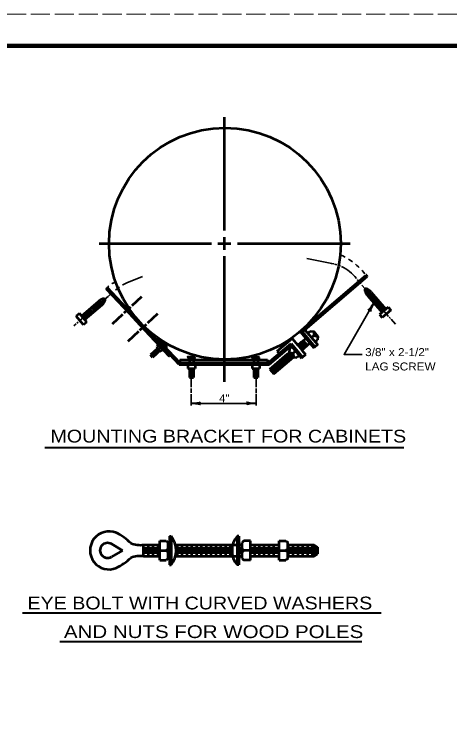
# Model space of a CAD drawing. Extents: x -1 to 679, y 0 to 440.
# Drawn here: x 353.6 to 490.2, y 220.2 to 440.2 of the extents above; entities that cross this region are included whole.
import ezdxf

# ---------------------------------------------------------------- set-up
doc = ezdxf.new("R2010")
doc.units = 0
doc.header["$PDMODE"] = 32
doc.header["$PDSIZE"] = 0.5
doc.linetypes.add('LONG_DASHED', pattern=[7.5, 6, -1.5])
doc.linetypes.add('SHORT_DASHED', pattern=[2.7, 1.5, -1.2])
doc.layers.add('1', color=7, linetype='Continuous', lineweight=53)
doc.layers.add('61', color=7, linetype='Continuous', lineweight=35)

msp = doc.modelspace()

# ---------------------------------------------------------------- linework, layer by layer
at = {"layer": '1'}
for p, q in [((419.561, 372.368), (419.561, 407.928)), ((419.561, 368.308), (419.561, 370.348)), ((380.261, 368.308), (415.501, 368.308)), ((417.481, 368.308), (421.501, 368.308)), ((419.561, 366.328), (419.561, 368.308)), ((423.581, 368.308), (458.881, 368.308)), ((443.221, 340.688), (463.921, 358.368)), ((443.941, 340.628), (464.261, 357.988)), ((462.401, 357.048), (462.721, 356.668)), ((405.341, 330.368), (382.921, 354.408)), ((460.861, 355.748), (461.181, 355.368)), ((388.101, 348.108), (382.561, 354.048)), ((463.541, 353.388), (464.301, 354.048)), ((463.661, 353.068), (464.421, 353.968)), ((464.081, 352.348), (465.081, 353.488)), ((464.321, 352.068), (468.901, 346.708)), ((464.621, 351.728), (465.621, 352.888)), ((465.161, 351.108), (466.161, 352.268)), ((465.481, 353.048), (470.061, 347.688)), ((380.101, 350.148), (374.741, 345.568)), ((379.741, 349.848), (380.901, 348.848)), ((380.361, 350.388), (381.501, 349.388)), ((381.081, 350.828), (381.981, 350.048)), ((381.401, 350.948), (382.061, 350.188)), ((390.601, 348.888), (393.661, 351.748)), ((465.681, 350.488), (466.681, 351.648)), ((466.201, 349.868), (467.221, 351.028)), ((466.741, 349.248), (467.741, 350.408)), ((381.061, 348.988), (375.721, 344.428)), ((377.261, 347.728), (378.421, 346.728)), ((377.881, 348.268), (379.041, 347.268)), ((378.501, 348.788), (379.661, 347.788)), ((379.121, 349.328), (380.281, 348.328)), ((388.101, 346.548), (390.181, 348.468)), ((388.461, 348.448), (388.101, 348.108)), ((389.641, 346.448), (388.101, 348.108)), ((467.261, 348.628), (468.281, 349.788)), ((467.801, 348.008), (468.801, 349.168)), ((470.821, 348.348), (468.141, 346.068)), ((468.321, 347.388), (469.341, 348.548)), ((469.561, 348.268), (468.421, 347.288)), ((470.821, 348.348), (471.641, 347.388)), ((374.081, 346.328), (373.121, 345.528)), ((375.401, 342.828), (373.121, 345.528)), ((376.361, 343.648), (374.081, 346.328)), ((376.281, 344.908), (375.301, 346.068)), ((375.401, 346.148), (376.561, 345.148)), ((376.021, 346.668), (377.181, 345.668)), ((376.641, 347.208), (377.801, 346.208)), ((384.461, 343.148), (387.741, 346.208)), ((390.001, 346.788), (389.641, 346.448)), ((393.081, 342.748), (389.641, 346.448)), ((395.561, 343.468), (398.621, 346.328)), ((468.141, 346.068), (468.961, 345.108)), ((471.641, 347.388), (468.961, 345.108)), ((376.361, 343.648), (375.401, 342.828)), ((393.061, 341.148), (395.121, 343.068)), ((393.441, 343.108), (393.081, 342.748)), ((395.001, 341.448), (394.641, 341.088)), ((389.401, 337.748), (392.681, 340.808)), ((443.221, 340.688), (447.481, 335.628)), ((443.941, 340.628), (447.861, 335.948)), ((445.641, 340.148), (446.401, 340.808)), ((446.801, 338.788), (447.561, 339.468)), ((447.481, 340.728), (448.781, 339.188)), ((399.181, 337.708), (398.621, 338.308)), ((405.521, 330.908), (398.641, 338.268)), ((433.241, 330.868), (440.421, 337.008)), ((436.041, 334.588), (440.721, 338.588)), ((440.421, 337.008), (444.001, 332.708)), ((443.081, 336.968), (444.361, 335.408)), ((443.641, 337.448), (444.941, 335.908)), ((443.681, 336.828), (444.341, 336.048)), ((443.801, 334.928), (446.281, 337.048)), ((444.221, 337.948), (444.981, 338.588)), ((444.221, 337.948), (445.521, 336.388)), ((444.261, 337.308), (444.921, 336.548)), ((447.941, 337.468), (448.701, 338.108)), ((398.481, 334.028), (397.801, 334.748)), ((398.661, 334.528), (398.341, 334.888)), ((398.921, 336.508), (398.361, 336.008)), ((398.521, 335.448), (399.221, 334.708)), ((399.601, 335.768), (399.041, 335.268)), ((400.281, 335.028), (399.721, 334.528)), ((436.041, 334.588), (436.681, 333.808)), ((440.681, 335.908), (439.901, 335.248)), ((441.801, 334.548), (441.041, 333.908)), ((443.121, 336.328), (443.761, 335.568)), ((397.021, 332.628), (396.321, 333.368)), ((397.261, 333.208), (396.901, 333.588)), ((397.801, 333.368), (397.101, 334.108)), ((397.981, 333.868), (397.621, 334.228)), ((409.161, 332.748), (409.161, 332.248)), ((409.801, 331.868), (410.301, 332.748)), ((429.341, 332.728), (429.341, 332.228)), ((429.961, 331.868), (430.481, 332.728)), ((435.001, 327.428), (441.141, 332.648)), ((438.101, 332.708), (439.421, 331.188)), ((438.681, 333.208), (439.981, 331.668)), ((438.721, 332.568), (439.381, 331.808)), ((439.261, 333.688), (440.561, 332.168)), ((439.301, 333.068), (439.941, 332.308)), ((439.821, 334.188), (441.141, 332.648)), ((439.861, 333.568), (440.521, 332.788)), ((442.941, 333.208), (442.181, 332.568)), ((444.961, 333.528), (443.621, 332.388)), ((405.341, 330.368), (433.481, 330.368)), ((405.521, 331.868), (432.981, 331.868)), ((405.521, 331.868), (405.521, 330.868)), ((405.521, 330.868), (433.241, 330.868)), ((408.041, 330.368), (408.041, 329.108)), ((408.541, 331.628), (408.541, 331.128)), ((409.801, 331.628), (409.801, 331.128)), ((410.301, 330.368), (410.301, 329.108)), ((428.201, 330.348), (428.201, 329.088)), ((428.701, 331.608), (428.701, 331.108)), ((429.961, 331.608), (429.961, 331.108)), ((430.481, 330.348), (430.481, 329.088)), ((432.981, 331.868), (432.981, 330.868)), ((435.221, 330.268), (436.541, 328.728)), ((435.801, 330.748), (437.121, 329.228)), ((435.841, 330.128), (436.501, 329.348)), ((436.381, 331.248), (437.681, 329.708)), ((436.421, 330.608), (437.081, 329.848)), ((436.961, 331.728), (438.261, 330.208)), ((437.001, 331.108), (437.641, 330.348)), ((437.521, 332.228), (438.841, 330.688)), ((437.561, 331.588), (438.221, 330.828)), ((438.141, 332.088), (438.801, 331.328)), ((408.041, 329.108), (410.301, 329.108)), ((408.541, 329.108), (408.541, 326.328)), ((408.541, 328.348), (409.801, 328.348)), ((408.781, 328.748), (409.541, 328.748)), ((408.781, 328.008), (409.541, 328.008)), ((409.801, 329.108), (409.801, 326.328)), ((428.201, 329.088), (430.481, 329.088)), ((428.701, 329.088), (428.701, 326.328)), ((428.701, 328.348), (429.961, 328.348)), ((428.961, 328.748), (429.721, 328.748)), ((428.961, 327.988), (429.721, 327.988)), ((429.961, 329.088), (429.961, 326.328)), ((433.701, 328.948), (435.001, 327.428)), ((434.081, 329.288), (435.381, 327.748)), ((434.081, 329.288), (435.381, 327.748)), ((434.661, 329.768), (435.961, 328.228)), ((434.701, 329.148), (435.341, 328.368)), ((435.261, 329.628), (435.921, 328.868)), ((408.541, 327.588), (409.801, 327.588)), ((408.541, 326.828), (409.801, 326.828)), ((408.541, 326.328), (409.801, 326.328)), ((408.781, 327.188), (409.541, 327.188)), ((428.701, 327.568), (429.961, 327.568)), ((428.701, 326.828), (429.961, 326.828)), ((428.701, 326.328), (429.961, 326.328)), ((428.961, 327.188), (429.721, 327.188)), ((399.251, 275.106), (401.271, 275.106)), ((402.271, 276.606), (402.271, 267.546)), ((402.271, 276.606), (402.791, 276.606)), ((402.791, 276.606), (402.791, 267.546)), ((423.511, 276.606), (423.511, 267.546)), ((424.011, 276.606), (423.511, 276.606)), ((424.011, 276.606), (424.011, 267.546)), ((425.631, 275.126), (425.031, 274.606)), ((427.651, 275.126), (425.631, 275.126)), ((436.711, 275.126), (438.731, 275.126)), ((438.731, 275.126), (439.331, 274.606)), ((387.591, 272.106), (384.091, 274.126)), ((394.211, 270.306), (394.211, 273.846)), ((394.211, 273.846), (399.231, 273.846)), ((394.971, 271.066), (394.971, 273.086)), ((395.731, 270.306), (395.731, 273.846)), ((396.491, 271.066), (396.491, 273.086)), ((397.231, 270.306), (397.231, 273.846)), ((397.991, 271.066), (397.991, 273.086)), ((398.751, 270.306), (398.751, 273.846)), ((401.871, 272.586), (401.871, 274.606)), ((401.871, 273.846), (402.251, 273.846)), ((404.171, 273.846), (424.971, 273.846)), ((404.791, 270.306), (404.791, 273.846)), ((405.551, 271.066), (405.551, 273.086)), ((406.311, 270.306), (406.311, 273.846)), ((407.071, 271.066), (407.071, 273.086)), ((407.831, 270.306), (407.831, 273.846)), ((408.571, 271.066), (408.571, 273.086)), ((409.331, 270.306), (409.331, 273.846)), ((410.091, 271.066), (410.091, 273.086)), ((410.851, 270.306), (410.851, 273.846)), ((411.611, 271.066), (411.611, 273.086)), ((412.351, 270.306), (412.351, 273.846)), ((413.111, 271.066), (413.111, 273.086)), ((413.871, 270.306), (413.871, 273.846)), ((414.631, 271.066), (414.631, 273.086)), ((415.391, 270.306), (415.391, 273.846)), ((416.131, 271.066), (416.131, 273.086)), ((416.891, 270.306), (416.891, 273.846)), ((417.651, 271.066), (417.651, 273.086)), ((418.411, 270.306), (418.411, 273.846)), ((419.171, 271.066), (419.171, 273.086)), ((419.911, 270.306), (419.911, 273.846)), ((420.671, 271.066), (420.671, 273.086)), ((421.431, 270.306), (421.431, 273.846)), ((424.471, 271.066), (424.471, 273.086)), ((425.031, 272.606), (425.031, 274.606)), ((427.571, 273.846), (436.671, 273.846)), ((428.231, 271.066), (428.231, 273.086)), ((428.991, 270.306), (428.991, 273.846)), ((429.751, 271.066), (429.751, 273.086)), ((430.511, 270.306), (430.511, 273.846)), ((431.251, 271.066), (431.251, 273.086)), ((432.011, 270.306), (432.011, 273.846)), ((432.771, 271.066), (432.771, 273.086)), ((433.531, 270.306), (433.531, 273.846)), ((434.291, 271.066), (434.291, 273.086)), ((435.031, 270.306), (435.031, 273.846)), ((435.791, 271.066), (435.791, 273.086)), ((439.291, 273.846), (447.631, 273.846)), ((439.331, 272.606), (439.331, 274.606)), ((439.571, 270.306), (439.571, 273.846)), ((440.331, 271.066), (440.331, 273.086)), ((441.091, 270.306), (441.091, 273.846)), ((441.851, 271.066), (441.851, 273.086)), ((442.591, 270.306), (442.591, 273.846)), ((443.351, 271.066), (443.351, 273.086)), ((444.111, 270.306), (444.111, 273.846)), ((444.871, 271.066), (444.871, 273.086)), ((445.631, 270.306), (445.631, 273.846)), ((446.371, 271.066), (446.371, 273.086)), ((447.131, 270.306), (447.131, 273.846)), ((447.631, 273.846), (447.631, 270.306)), ((447.631, 273.846), (448.651, 273.086)), ((448.151, 273.466), (448.151, 270.686)), ((448.651, 273.086), (448.651, 271.066)), ((387.591, 272.106), (384.091, 270.086)), ((399.251, 272.086), (401.271, 272.086)), ((401.871, 272.586), (401.871, 271.566)), ((401.871, 269.566), (401.871, 271.566)), ((425.031, 272.606), (425.031, 271.586)), ((425.031, 269.566), (425.031, 271.586)), ((427.651, 272.086), (425.631, 272.086)), ((436.711, 272.086), (438.731, 272.086)), ((439.331, 272.606), (439.331, 271.586)), ((439.331, 269.566), (439.331, 271.586)), ((447.631, 270.306), (448.651, 271.066)), ((394.211, 270.306), (399.231, 270.306)), ((399.251, 269.046), (401.271, 269.046)), ((401.871, 269.566), (401.271, 269.046)), ((401.871, 270.306), (402.271, 270.306)), ((404.171, 270.306), (425.031, 270.306)), ((425.031, 269.566), (425.631, 269.066)), ((427.651, 269.066), (425.631, 269.066)), ((436.711, 269.066), (438.731, 269.066)), ((439.331, 269.566), (438.731, 269.066)), ((439.331, 270.306), (447.631, 270.306)), ((402.271, 267.546), (402.791, 267.546)), ((424.011, 267.546), (423.511, 267.546))]:
    msp.add_line(p, q, dxfattribs=at)
at = {"layer": '1', "lineweight": 13}
for p, q in [((421.501, 368.308), (421.521, 368.308)), ((393.861, 341.928), (394.221, 342.248))]:
    msp.add_line(p, q, dxfattribs=at)
at = {"layer": '1', "lineweight": 35}
for p, q in [((445.341, 363.568), (453.201, 362.048)), ((452.961, 362.088), (453.761, 361.928)), ((393.841, 357.928), (388.921, 355.988)), ((461.301, 356.788), (462.281, 355.628)), ((462.601, 355.248), (464.701, 352.808)), ((464.421, 353.228), (464.821, 352.768)), ((465.281, 352.108), (470.961, 345.468)), ((378.861, 348.108), (383.161, 351.768)), ((378.141, 347.488), (378.601, 347.888)), ((373.881, 343.848), (377.981, 347.348)), ((373.281, 343.348), (373.681, 343.668)), ((471.161, 345.248), (471.561, 344.768)), ((471.721, 344.588), (473.081, 342.988)), ((372.301, 342.508), (373.081, 343.168)), ((409.121, 326.328), (409.121, 323.248)), ((429.421, 326.368), (429.421, 323.288)), ((409.121, 322.828), (409.121, 321.508)), ((429.421, 322.868), (429.421, 321.548)), ((409.121, 321.128), (409.121, 317.508)), ((429.421, 321.168), (429.421, 317.548)), ((409.121, 318.208), (429.361, 318.208))]:
    msp.add_line(p, q, dxfattribs=at)
at = {"layer": '1', "lineweight": 40}
for p, q in [((363.269, 304.328), (475.717, 304.328)), ((356.23, 252.546), (468.616, 252.546)), ((367.972, 243.526), (462.577, 243.526))]:
    msp.add_line(p, q, dxfattribs=at)
at = {"layer": '1'}
for points in [[(419.561, 324.908), (419.561, 332.108), (419.561, 364.308)], [(402.161, 333.028), (394.641, 341.088), (393.081, 342.748)], [(444.701, 341.288), (448.641, 336.608), (447.481, 335.628)], [(446.401, 340.808), (447.481, 340.728), (447.561, 339.468), (448.781, 339.188), (448.701, 338.108)], [(440.721, 338.588), (442.501, 336.468), (443.801, 334.928), (444.961, 333.528)], [(442.501, 336.468), (443.641, 337.448), (444.221, 337.948)], [(398.521, 335.448), (397.421, 334.408), (396.321, 333.368)], [(399.221, 334.708), (398.121, 333.668), (397.021, 332.628)], [(398.361, 336.008), (398.521, 335.448), (399.041, 335.268), (399.221, 334.708), (399.721, 334.528)], [(433.481, 330.368), (440.381, 336.248), (443.621, 332.388)], [(439.901, 335.248), (439.821, 334.188), (441.041, 333.908), (441.141, 332.648), (442.181, 332.568)], [(408.541, 331.868), (408.041, 332.748), (410.301, 332.748)], [(428.701, 331.868), (428.201, 332.728), (430.481, 332.728)], [(433.701, 328.948), (439.261, 333.688), (439.821, 334.188)], [(399.251, 269.046), (399.251, 272.086), (399.251, 275.106)], [(401.271, 275.106), (401.871, 274.606), (401.871, 272.586), (401.271, 272.086), (401.871, 271.566)], [(427.651, 269.066), (427.651, 272.086), (427.651, 275.126)], [(436.711, 269.066), (436.711, 272.086), (436.711, 275.126)], [(425.031, 272.606), (425.631, 272.086), (425.031, 271.586)], [(439.331, 272.606), (438.731, 272.086), (439.331, 271.586)], [(427.611, 270.306), (436.671, 270.306), (436.711, 270.306)]]:
    msp.add_lwpolyline(points, dxfattribs=at)
at = {"layer": '1', "lineweight": 35}
msp.add_lwpolyline([(462.701, 333.548), (457.021, 333.548), (466.341, 349.708)], dxfattribs=at)
at = {"layer": '1'}
msp.add_circle((419.664, 368.287), 36.288, dxfattribs=at)
at = {"layer": '1', "linetype": 'SHORT_DASHED', "lineweight": 35}
for centre, radius, start, end in [((446.674, 345.165), 21.69, 39.09076, 64.25674), ((387.401, 350.48), 6.088, 107.18277, 136.93055), ((399.617, 335.348), 23.253, 117.40174, 135.04708)]:
    msp.add_arc(centre, radius, start, end, dxfattribs=at)
at = {"layer": '1', "lineweight": 35}
for start, end in [(72.09704, 75.39826), (66.7088, 70.55356), (37.97532, 65.20978), (34.61481, 35.37094)]:
    msp.add_arc((450.83, 349.56), 12.719, start, end, dxfattribs=at)
at = {"layer": '1'}
for centre, radius, start, end in [((463.949, 358.221), 0.147, 341.35274, 99.6479), ((464.227, 358.127), 0.147, 161.35274, 279.6479), ((464.113, 358.03), 0.147, 341.35274, 99.6479), ((382.882, 354.256), 0.147, 75.35274, 193.6479), ((382.777, 354.364), 0.147, 255.35274, 13.6479), ((382.702, 354.08), 0.147, 75.35274, 193.6479), ((464.491, 353.662), 0.994, 154.26025, 195.83671), ((466.584, 354.331), 3.191, 197.13743, 224.94055), ((463.878, 353.139), 0.994, 64.26025, 105.83671), ((462.617, 350.829), 3.625, 37.7559, 62.16939), ((382.348, 347.893), 3.191, 107.13743, 134.94055), ((378.847, 351.859), 3.625, 307.7559, 332.16939), ((381.68, 349.985), 0.994, 64.26025, 105.83671), ((381.157, 350.598), 0.994, 334.26025, 15.83671), ((398.387, 337.996), 0.147, 73.35274, 191.6479), ((398.573, 338.166), 0.147, 73.35274, 191.6479), ((398.471, 338.277), 0.147, 253.35274, 11.6479), ((398.471, 338.277), 0.147, 11.56977, 11.63706), ((399.609, 335.794), 1.805, 346.12036, 99.8792), ((402.286, 333.096), 0.147, 86.35274, 204.6479), ((402.162, 333.181), 0.147, 266.35274, 24.6479), ((402.304, 333.389), 0.147, 266.35274, 24.6479), ((383.37, 272.117), 5.96, 67.37581, 292.62419), ((379.006, 263.665), 15.46, 43.69833, 64.49446), ((397.211, 272.078), 7.185, 320.85375, 39.14625), ((429.074, 272.078), 7.185, 140.85375, 219.14625), ((382.885, 272.11), 2.352, 58.9871, 301.0129), ((393.397, 283.677), 9.87, 250.99574, 274.75423), ((377.334, 283.147), 18.511, 296.74116, 313.96028), ((393.397, 260.49), 9.87, 85.24577, 109.00426)]:
    msp.add_arc(centre, radius, start, end, dxfattribs=at)
at = {"layer": '1', "lineweight": 40}
for centre, major_axis, ratio, start_param, end_param in [((465.596, 348.84), (-1.039, -1.445), 0.07063, 6.2823074, 8.5597026), ((466.037, 348.62), (0.764, 1.638), 0.122415, 0.8963533, 3.1415927), ((410.214, 318.482), (-1.8, -0.157), 0.122415, 0.8963533, 3.1415927), ((410.244, 317.99), (1.77, -0.177), 0.07063, 6.2823074, 8.5597026), ((428.262, 317.925), (1.8, 0.157), 0.122415, 0.8963533, 3.1415927), ((428.233, 318.417), (-1.77, 0.177), 0.07063, 6.2823074, 8.5597026)]:
    msp.add_ellipse(centre, major_axis=major_axis, ratio=ratio, start_param=start_param, end_param=end_param, dxfattribs=at)
at = {"layer": '1'}
msp.add_point((398.621, 338.308), dxfattribs=at)
at = {"layer": '61', "linetype": 'LONG_DASHED', "lineweight": 13}
msp.add_line((-1.129, 440.242), (678.891, 440.242), dxfattribs=at)
at = {"layer": '61', "lineweight": 158}
msp.add_lwpolyline([(667.911, 430.242), (28.871, 430.242), (28.871, 10.222)], dxfattribs=at)

# ---------------------------------------------------------------- texts
at = {"layer": '1'}
for s, height, width, p in [('3/8" x 2-1/2"', 2.5, 1.1, (463.603, 333.022)), ('LAG SCREW', 2.5, 1.1, (463.603, 328.522)), ('4"', 2.52, 1.05, (417.881, 318.548)), ('MOUNTING BRACKET FOR CABINETS', 4, 1.15, (365.024, 305.935)), ('EYE BOLT WITH CURVED WASHERS', 4, 1.15, (357.824, 253.621)), ('AND NUTS FOR WOOD POLES', 4, 1.2, (369.23, 244.644))]:
    msp.add_text(s, height=height, dxfattribs=dict(at, width=width)).set_placement(p)

doc.saveas('drawing.dxf')
